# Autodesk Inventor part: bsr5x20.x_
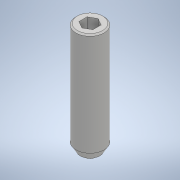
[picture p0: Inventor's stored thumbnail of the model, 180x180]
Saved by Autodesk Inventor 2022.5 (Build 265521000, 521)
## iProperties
Created: 2020-01
Part Number: bsr5x20.x_
Material: 一般
Document SubType Name: Modeling
Designer: ImaoCorp
Density: 1 g/cm^3
Appearance: 既定
Sending System: SOLIDWORKS 2018-2018316
MC: AMD64
MC_MODEL: Intel64 Family 6 Model 60 Stepping 3, GenuineIntel
OS: Windows_NT
FRU: Parasolid Version 30.0, build 310,  6- 8-2018
FORMAT: text
GUISE: transmit
KEY: bsr5x20
FILE: bsr5x20.x_t
DATE: Thu Jan 23 16:47:20 2020
Author: ImaoCorp
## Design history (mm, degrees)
feature "Base1"
node "ソリッド1"
